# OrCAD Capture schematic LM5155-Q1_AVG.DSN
size D; title: LM5155-Q1 2.2-MHz Wide Input Nonsynchronous Boost, SEPIC,; rev: 1.0; note: Datasheet: SNVSAY4B     EVM: SNVU608; note: Synchronous Step Down Converter
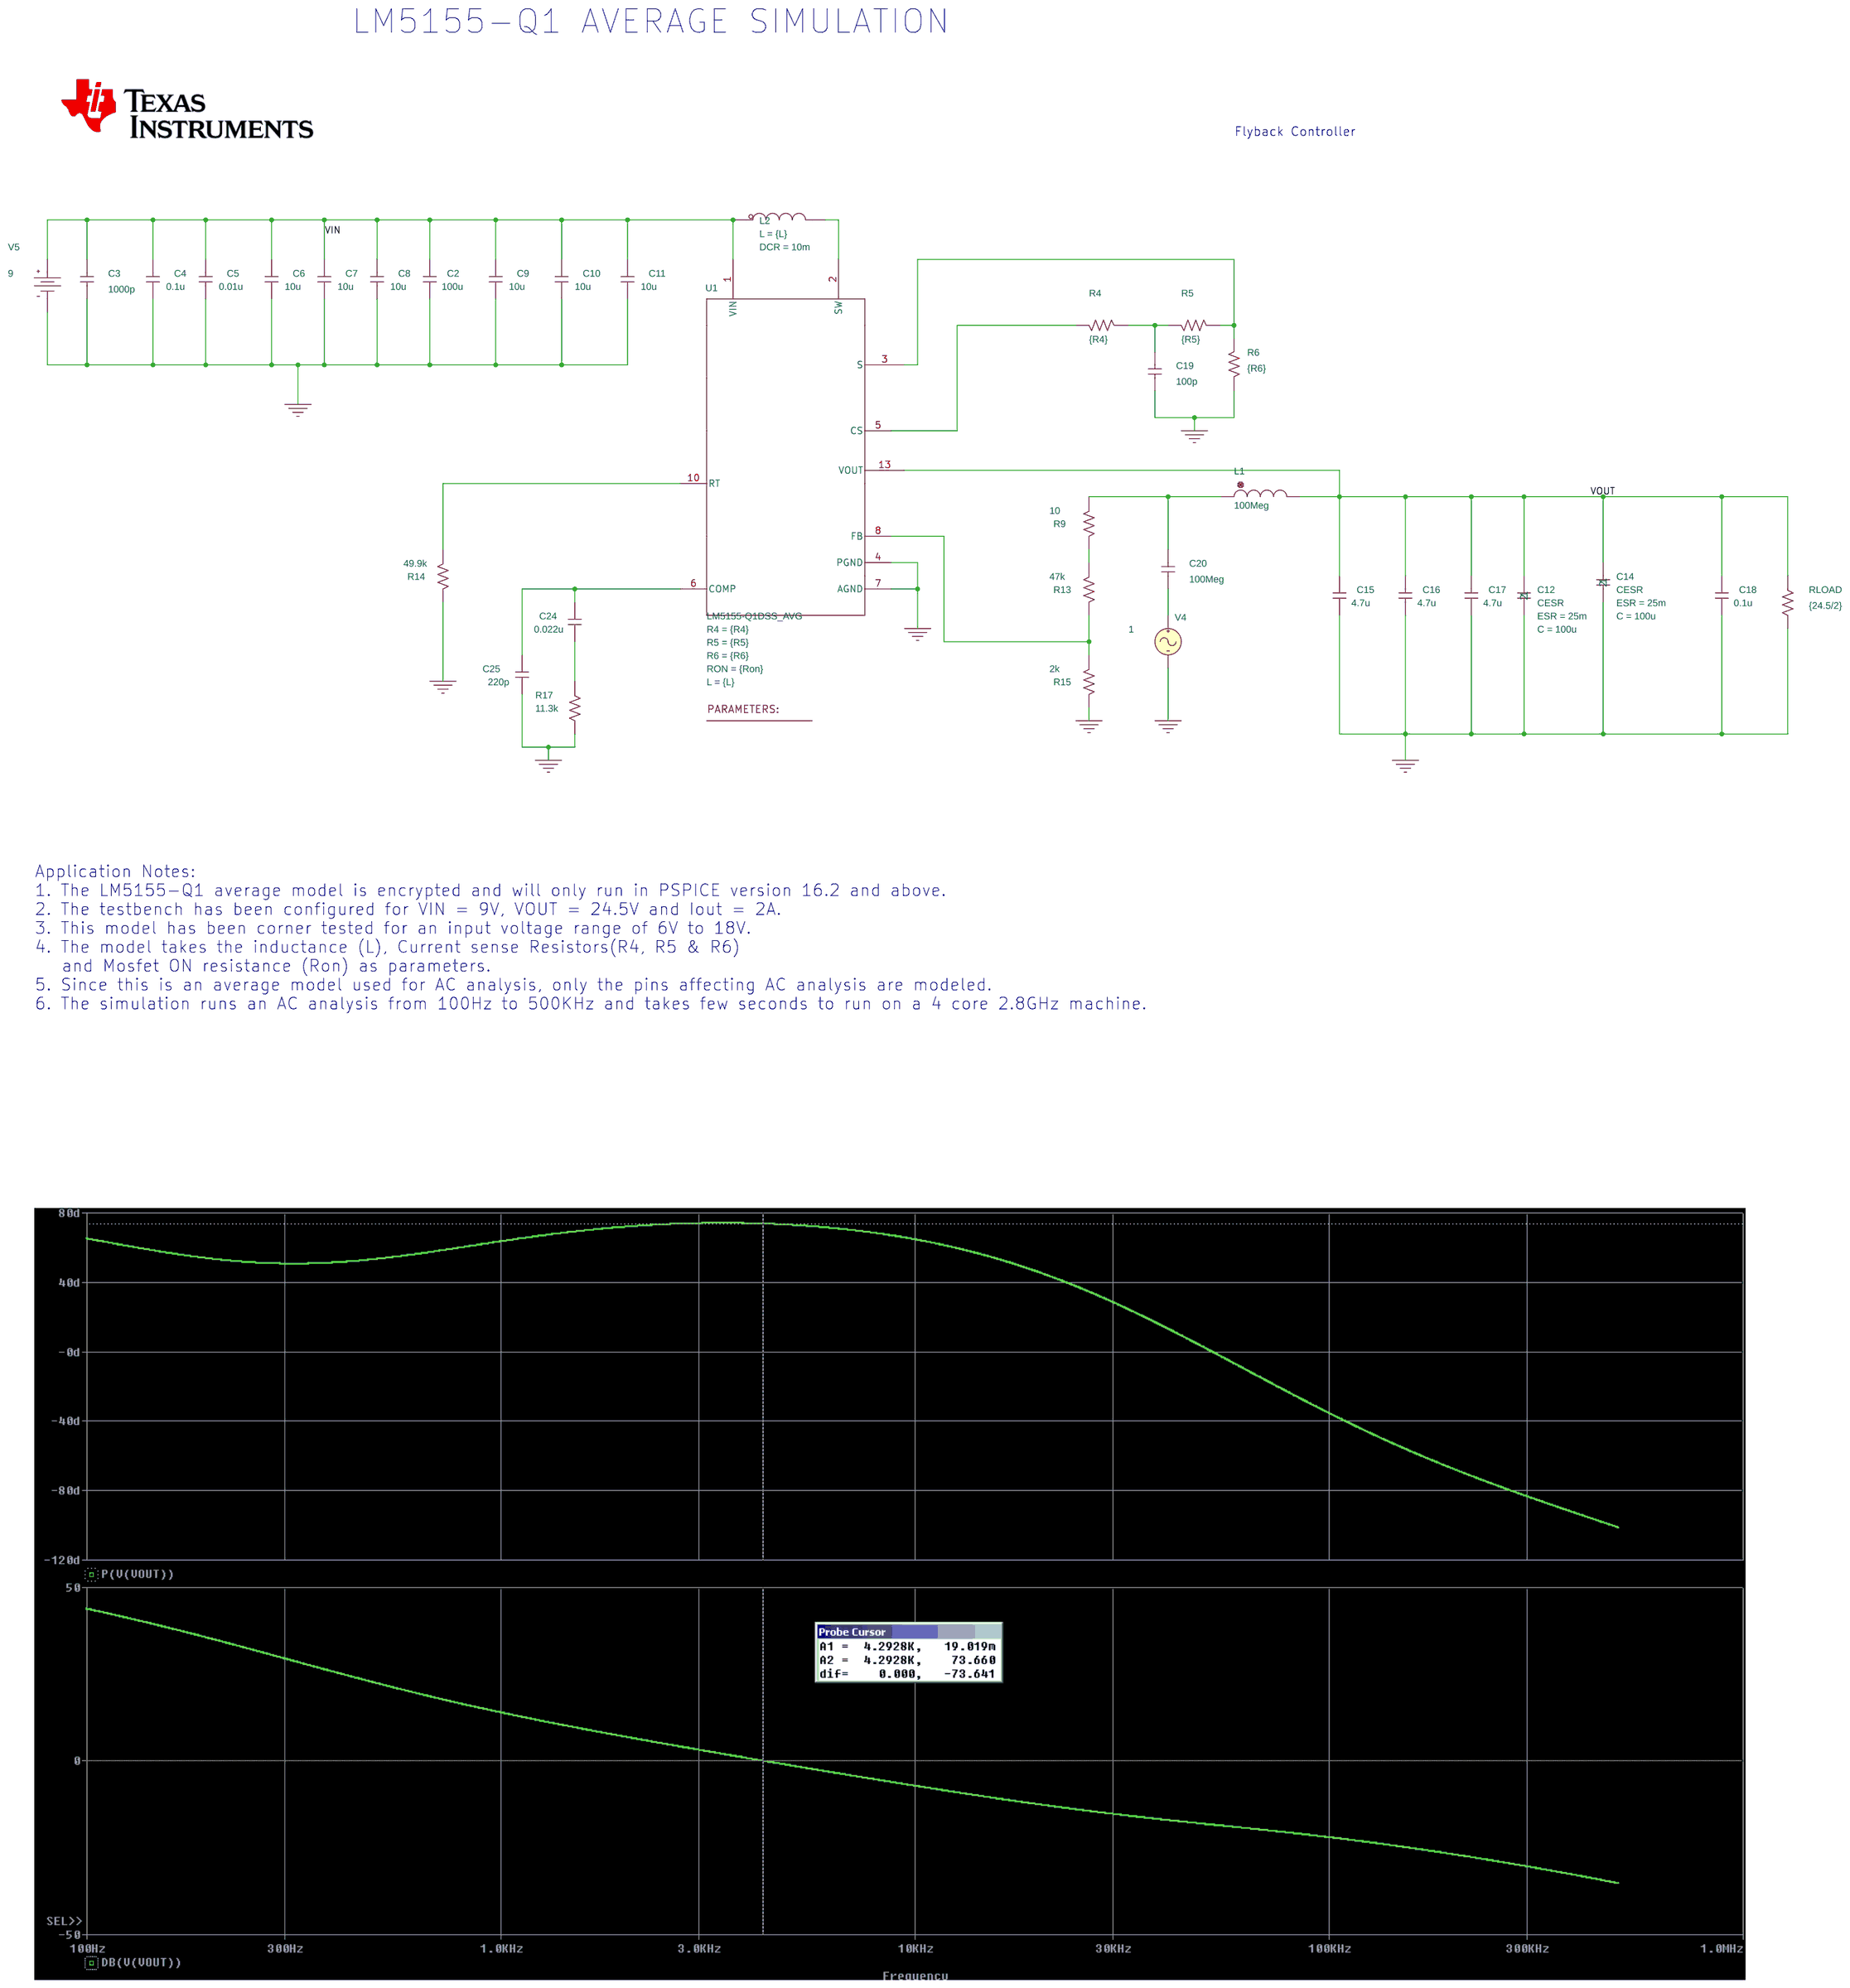
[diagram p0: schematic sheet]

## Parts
1  PARAM
C2  100u  [RAD/CK05]
C3  1000p  [RAD/CK05]
C4  0.1u  [RAD/CK05]
C5  0.01u  [RAD/CK05]
C6  10u  [RAD/CK05]
C7  10u  [RAD/CK05]
C8  10u  [RAD/CK05]
C9  10u  [RAD/CK05]
C10  10u  [RAD/CK05]
C11  10u  [RAD/CK05]
C12  CESR
C14  CESR
C15  4.7u  [RAD/CK05]
C16  4.7u  [RAD/CK05]
C17  4.7u  [RAD/CK05]
C18  0.1u  [RAD/CK05]
C19  100p  [RAD/CK05]
C20  100Meg  [RAD/CK05]
C24  0.022u  [RAD/CK05]
C25  220p  [RAD/CK05]
L1  100Meg  [DISC/.350x.175/LS.200x.100/.034]
L2  LDCR
R4  {R4}  [AX/RC05]
R5  {R5}  [AX/RC05]
R6  {R6}  [AX/RC05]
R9  10  [AX/RC05]
R13  47k  [AX/RC05]
R14  49.9k  [AX/RC05]
R15  2k  [AX/RC05]
R17  11.3k  [AX/RC05]
RLOAD  {24.5/2}  [AX/RC05]
U1  LM5155-Q1DSS_AVG  [DSS0012C]
V4  VAC
V5  VDC

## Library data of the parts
1 = PARAM: L: 6.8u; R4: 1u; R5: 100; R6: 0.008; Ron: 5.7m
C2-C11 C15-C20 C24 C25 = C
C12 = CESR: C: 100u; ESR: 25m; PSpiceTemplate: X^@REFDES %1 %2 @MODEL PARAMS: ?C|C=@C||C=10U| ?ESR|ESR=@ESR||ESR=2M|
C14 = CESR_1: C: 100u; ESR: 25m; PSpiceTemplate: X^@REFDES %1 %2 @MODEL PARAMS: ?C|C=@C||C=10U| ?ESR|ESR=@ESR||ESR=2M|
L1 = L
L2 = LDCR_0: DCR: 10m; L: {L}; PSpiceTemplate: X^@REFDES %IN %OUT @MODEL PARAMS:  ?L|L=@L||L=1u|  ?DCR|DCR=@DCR||DCR=0.01|
R4-R6 R9 R13-R15 R17 RLOAD = R
U1 = LM5155-Q1DSS_AVG: L: {L}; R4: {R4}; R5: {R5}; R6: {R6}; RON: {Ron}
V4 = VAC: ACMAG: 1; ACPHASE: 0
V5 = VDC: DC: 9

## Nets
VIN: C2.1 C3.1 C4.1 C5.1 C6.1 C7.1 C8.1 C9.1 C10.1 C11.1 L2.1(IN) U1.1(VIN) V5.0(+)
0: C2.2 C3.2 C4.2 C5.2 C6.2 C7.2 C8.2 C9.2 C10.2 C11.2 C12.2 C14.2 C15.2 C16.2 C17.2 C18.2 C19.2 C25.2 R6.1 R14.2 R15.2 R17.2 RLOAD.2 U1.4(PGND) U1.7(AGND) V4.2(-) V5.1(-)
VOUT: C12.1 C14.1 C15.1 C16.1 C17.1 C18.1 L1.2 RLOAD.1 U1.13(VOUT)
N16770483: C20.1 L1.1 R9.1
N16770581: R13.2 R15.1 U1.8(FB)
N16770593: C20.2 V4.1(+)
N16770707: R9.2 R13.1
N16771591: R4.2 U1.5(CS)
N16771595: C19.1 R4.1 R5.2
N16771677: R5.1 R6.2 U1.3(S)
N16775899: L2.3(OUT) U1.2(SW)
N16781250: R14.1 U1.10(RT)
N16781617: C24.2 R17.1
N16781620: C24.1 C25.1 U1.6(COMP)

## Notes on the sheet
- LM5155-Q1 AVERAGE SIMULATION
- Flyback Controller
- Application Notes:
  1. The LM5155-Q1 average model is encrypted and will only run in PSPICE version 16.2 and above.
  2. The testbench has been configured for VIN = 9V, VOUT = 24.5V and Iout = 2A.
  3. This model has been corner tested for an input voltage range of 6V to 18V.
  4. The model takes the inductance (L), Current sense Resistors(R4, R5 & R6)
     and Mosfet ON resistance (Ron) as parameters.
  5. Since this is an average model used for AC analysis, only the pins affecting AC analysis are modeled.
  6. The simulation runs an AC analysis from 100Hz to 500KHz and takes few seconds to run on a 4 core 2.8GHz machine.
